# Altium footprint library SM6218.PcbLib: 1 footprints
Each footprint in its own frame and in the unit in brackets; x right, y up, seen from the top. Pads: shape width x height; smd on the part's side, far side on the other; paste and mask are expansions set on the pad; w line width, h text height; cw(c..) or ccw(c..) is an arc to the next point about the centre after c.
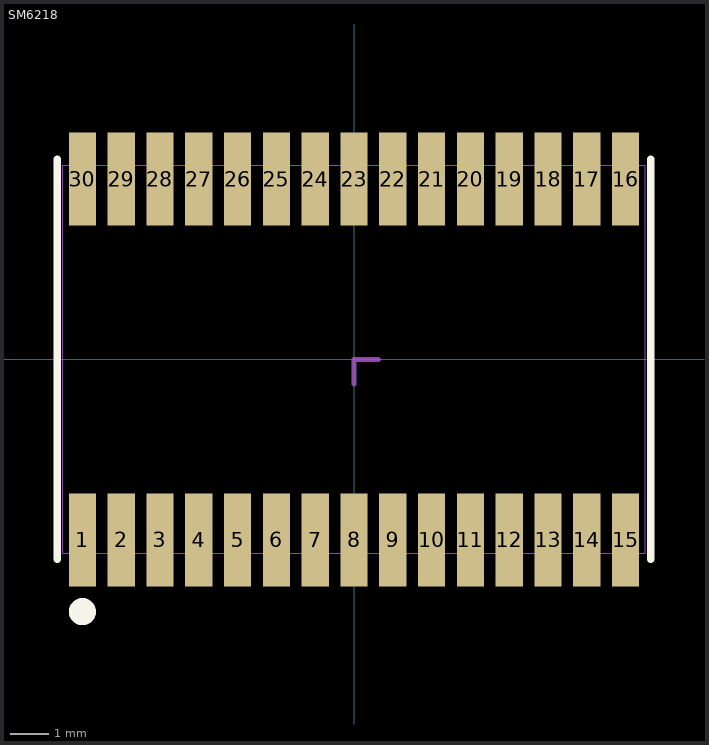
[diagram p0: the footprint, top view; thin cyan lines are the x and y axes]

## SM6218 [mm]
height 3
pads (30):
  rect 0.7x2.4 smd: 1(-7,-4.65) 2(-6,-4.65) 3(-5,-4.65) 4(-4,-4.65) 5(-3,-4.65) 6(-2,-4.65) 7(-1,-4.65) 8(0,-4.65) 9(1,-4.65) 10(2,-4.65) 11(3,-4.65) 12(4,-4.65) 13(5,-4.65) 14(6,-4.65) 15(7,-4.65) 16(7,4.65) 17(6,4.65) 18(5,4.65) 19(4,4.65) 20(3,4.65) 21(2,4.65) 22(1,4.65) 23(0,4.65) 24(-1,4.65) 25(-2,4.65) 26(-3,4.65) 27(-4,4.65) 28(-5,4.65) 29(-6,4.65) 30(-7,4.65)
Top Overlay:
  circle w0.5: c-7,-6.5 r0.1
  lines w0.2: -7.65,-5.15 -7.65,5.15 ; 7.65,-5.15 7.65,5.15
Mechanical 15:
  lines w0.003: -7.5,-5 7.5,-5 7.5,5 -7.5,5 -7.5,-5
  lines w0.127: 0,-0.635 0,0 0.635,0
3D body: height 3, standoff 0, extent -7.5,-5 7.5,5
